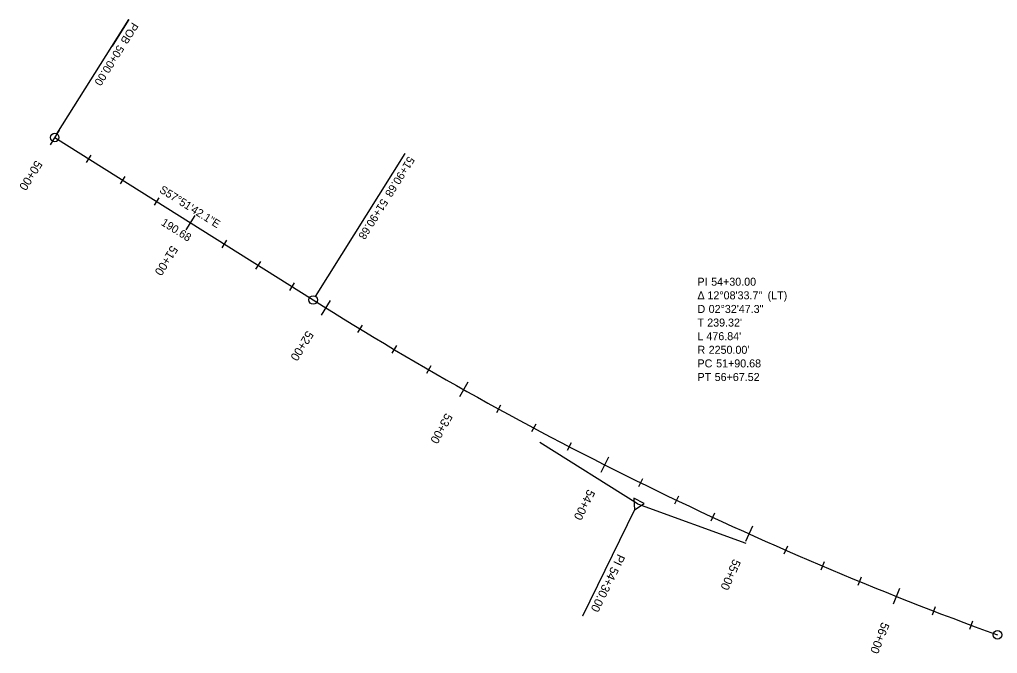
# Model space of a CAD drawing. Extents: x 2301963 to 2307911, y 760768 to 761974.
# Drawn here: x 2301963 to 2302574, y 761579 to 761974 of the extents above; entities that cross this region are included whole.
import ezdxf

# ---------------------------------------------------------------- set-up
doc = ezdxf.new("R2010")
doc.units = 0
for name, color, linetype in [('Default', 7, 'Continuous'), ('Draft_Bearing Label', 7, 'Continuous'), ('Draft_Curve Data Label', 7, 'Continuous'), ('Draft_Station Cardinal Lines', 7, 'Continuous'), ('Draft_Station Cardinal Points', 7, 'Continuous'), ('Draft_Station Labels Major', 7, 'Continuous'), ('Draft_Station Ticks Major', 7, 'Continuous'), ('Draft_Station Ticks Minor', 7, 'Continuous'), ('Geom_Secondary', 7, 'Continuous')]:
    doc.layers.add(name, color=color, linetype=linetype)

msp = doc.modelspace()

# ---------------------------------------------------------------- linework, layer by layer
at = {"layer": 'Default'}
msp.add_line((2301985.09, 761900.64), (2302146.55, 761799.21), dxfattribs=at)
msp.add_arc((2303343.47, 763704.43), 2250, 237.8617, 250.00439, dxfattribs=at)
at = {"layer": 'Draft_Station Cardinal Lines'}
for p, q in [((2302147.97, 761801.47), (2302204.01, 761890.66)), ((2302349.2, 761671.9), (2302288.23, 761710.2)), ((2302349.2, 761671.9), (2302416.86, 761647.28)), ((2302347.35, 761668.12), (2302314.92, 761601.83))]:
    msp.add_line(p, q, dxfattribs=at)
msp.add_lwpolyline([(2302347.37, 761668.16), (2302353.35, 761672.18), (2302346.88, 761675.35)], close=True, dxfattribs=at)
at = {"layer": 'Draft_Station Cardinal Points'}
for p, q in [((2301986.51, 761902.9), (2302031.37, 761974.31)), ((2302031.37, 761974.31), (2302020.9, 761957.64)), ((2301985.09, 761900.64), (2301985.09, 761900.64)), ((2302204.01, 761890.66), (2302204.01, 761890.66)), ((2302146.55, 761799.21), (2302146.55, 761799.21)), ((2302349.2, 761671.9), (2302349.2, 761671.9)), ((2302314.92, 761601.83), (2302314.92, 761601.83))]:
    msp.add_line(p, q, dxfattribs=at)
for centre in [(2301985.09, 761900.64), (2302146.55, 761799.21), (2302574.09, 761590.06)]:
    msp.add_circle(centre, 2.67, dxfattribs=at)
at = {"layer": 'Draft_Station Ticks Major'}
for p, q in [((2301987.93, 761905.16), (2301982.28, 761896.17)), ((2302072.61, 761851.97), (2302066.96, 761842.97)), ((2302157.28, 761798.8), (2302151.67, 761789.78)), ((2302243.12, 761747.98), (2302237.91, 761738.72)), ((2302331.13, 761701.02), (2302326.34, 761691.54)), ((2302421.14, 761658.02), (2302416.77, 761648.34)), ((2302512.97, 761619.06), (2302509.04, 761609.19))]:
    msp.add_line(p, q, dxfattribs=at)
at = {"layer": 'Draft_Station Ticks Minor'}
for p, q in [((2302007.73, 761889.68), (2302004.79, 761885)), ((2302028.9, 761876.38), (2302025.96, 761871.71)), ((2302050.07, 761863.08), (2302047.13, 761858.41)), ((2302092.41, 761836.48), (2302089.47, 761831.81)), ((2302113.58, 761823.18), (2302110.64, 761818.51)), ((2302134.74, 761809.88), (2302131.81, 761805.21)), ((2302177.18, 761783.53), (2302174.32, 761778.81)), ((2302198.6, 761770.69), (2302195.79, 761765.94)), ((2302220.16, 761758.09), (2302217.4, 761753.31)), ((2302263.68, 761733.61), (2302261.03, 761728.77)), ((2302285.65, 761721.73), (2302283.05, 761716.86)), ((2302307.74, 761710.1), (2302305.2, 761705.2)), ((2302352.31, 761687.58), (2302349.88, 761682.63)), ((2302374.78, 761676.69), (2302372.4, 761671.71)), ((2302397.37, 761666.05), (2302395.05, 761661.05)), ((2302442.9, 761645.53), (2302440.69, 761640.48)), ((2302465.83, 761635.66), (2302463.67, 761630.57)), ((2302488.87, 761626.03), (2302486.77, 761620.93)), ((2302535.26, 761607.56), (2302533.28, 761602.4)), ((2302558.61, 761598.7), (2302556.68, 761593.53))]:
    msp.add_line(p, q, dxfattribs=at)
at = {"layer": 'Geom_Secondary'}
msp.add_line((2301985.09, 761900.64), (2302146.55, 761799.21), dxfattribs=at)
msp.add_arc((2303343.47, 763704.43), 2250, 237.8617, 250.00439, dxfattribs=at)

# ---------------------------------------------------------------- texts
at = {"layer": 'Draft_Bearing Label'}
for s, p in [('S57°51\'42.1"E', (2302050.03, 761866.79)), ('190.68', (2302051.12, 761846.31))]:
    msp.add_text(s, height=5, rotation=327.8617, dxfattribs=at).set_placement(p)
at = {"layer": 'Draft_Curve Data Label'}
for s, p in [('PI ', (2302386.69, 761808.11)), ('54+30.00', (2302395.23, 761808.11)), ('Δ ', (2302386.69, 761799.61)), ('12°08\'33.7"', (2302392.91, 761799.61)), (' (LT)', (2302428.64, 761799.61)), ('D ', (2302386.69, 761791.11)), ('02°32\'47.3"', (2302393.67, 761791.11)), ('T ', (2302386.69, 761782.61)), ("239.32'", (2302392.77, 761782.61)), ('L ', (2302386.69, 761774.11)), ("476.84'", (2302392.25, 761774.11)), ('R ', (2302386.69, 761765.61)), ("2250.00'", (2302393.67, 761765.61)), ('PC ', (2302386.69, 761757.11)), ('51+90.68', (2302398.33, 761757.11)), ('PT ', (2302386.69, 761748.61)), ('56+67.52', (2302397.43, 761748.61))]:
    msp.add_text(s, height=5, dxfattribs=at).set_placement(p)
at = {"layer": 'Draft_Station Cardinal Points'}
for s, height, rotation, p in [('POB ', 5, 237.8617, (2302033.48, 761972.99)), ('50+00.00', 5, 237.8617, (2302024.59, 761958.85)), ('51+90.68', 5, 237.8617, (2302206.11, 761889.33)), ('51+90.68', 5, 237.8617, (2302189.48, 761862.87)), ('PI ', 5.34, 243.93305, (2302336.89, 761641.02)), ('54+30.00', 5.34, 243.93305, (2302332.97, 761633.02))]:
    msp.add_text(s, height=height, rotation=rotation, dxfattribs=at).set_placement(p)
at = {"layer": 'Draft_Station Labels Major'}
for s, rotation, p in [('50+00', 237.8617, (2301973.26, 761886.82)), ('51+00', 237.8617, (2302057.93, 761833.62)), ('52+00', 238.09903, (2302142.68, 761780.39)), ('53+00', 240.64551, (2302229.35, 761728.94)), ('54+00', 243.19199, (2302318.22, 761681.39)), ('55+00', 245.73847, (2302409.11, 761637.84)), ('56+00', 248.28494, (2302501.85, 761598.37))]:
    msp.add_text(s, height=5.34, rotation=rotation, dxfattribs=at).set_placement(p)

doc.saveas('drawing.dxf')
